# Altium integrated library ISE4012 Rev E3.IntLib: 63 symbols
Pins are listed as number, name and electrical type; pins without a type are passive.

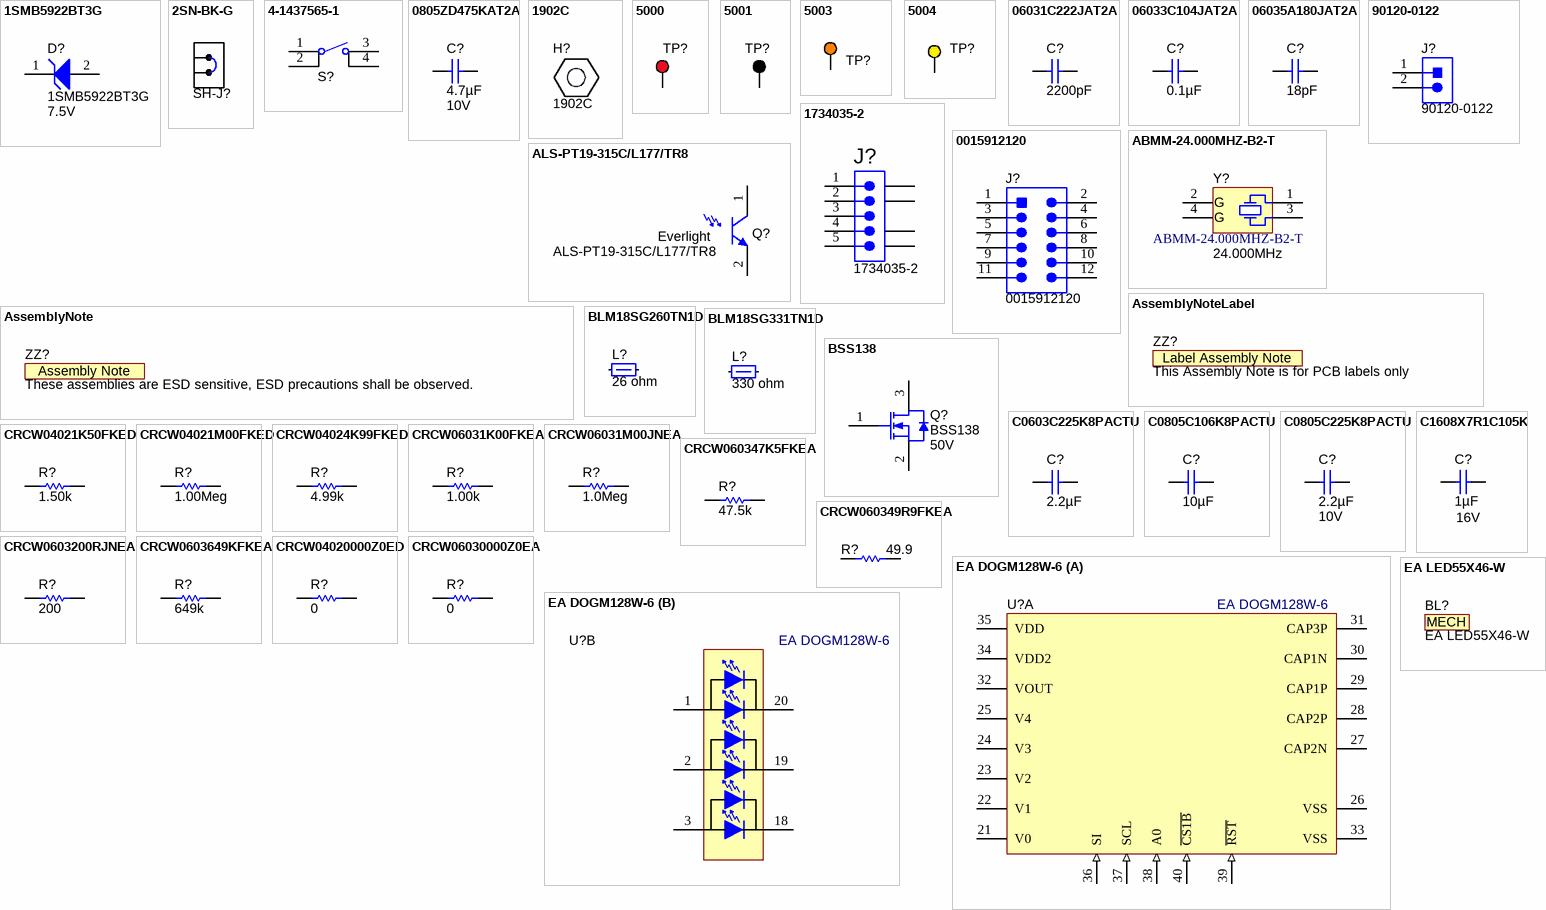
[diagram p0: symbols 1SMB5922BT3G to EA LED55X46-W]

## 1SMB5922BT3G
designator D?  value 7.5V
Diode, Zener, 7.5V, 550mW, SMB; Manufacturer: ON Semiconductor; U/M: EA; Power_W: 0.55; Vz_V: 7.5; Value1: 0.55W; RJA_CperW: 226
signal-integrity model Diode
simulation model 1smb5922bt3
footprint SMB
pins: 1 K, 2 A

## 2SN-BK-G
designator SH-J?  (value not drawn)
Shunt, 2mm, Gold plated, Black; Manufacturer: Samtec; Value: 1x2; Note: You can "mate" this to a header by matching the designator.  i.e. use SH-J3 for header J3
footprint 2SN-BK-G

## 4-1437565-1
designator S?  (value not drawn)
Switch, Tactile, SPST-NO, 0.05A, 12V, SMT; Manufacturer: TE Connectivity; SymbolCreator: a0412235; VDC_V: 12; SwitchFunction: Off-Mom; PositionCount: 1; CurrentRating_mA: 50
footprint SW_FSM4JSMA
pins: 1, 2, 3, 4

## 0805ZD475KAT2A
designator C?  ValueDisplayed: 4.7µF  Value2: 10V  (hidden comment: 0805ZD475KAT2A)
CAP, CERM, 4.7uF, 10V, +/-10%, X5R, 0805; Manufacturer: AVX; Polarized: N; CompType: Capacitor; U/M: EA; Cap_F: 0.0000047; Tolerance_%: 10; ESR_Ohm: 0.007; Value1: 0.007 ohm; TaMin_C: -55; TaMax_C: 85; Cap_Case: 0805
signal-integrity model Cap
simulation model Cap
footprint 0805_HV
footprint 0805
footprint 0805M
footprint 0805L
pins: 1, 2

## 1902C
designator H?
Standoff, Hex, 0.5"L #4-40 Nylon; Manufacturer: Keystone; CompType: Hardware
footprint Keystone_1902C

## 5000
designator TP?  (value not drawn)
Test Point, Miniature, Red, TH; Manufacturer: Keystone; CompType: Test Point Loop; U/M: EA
footprint Keystone5000
pins: 1

## 5001
designator TP?, comment 5000  (value not drawn)
Test Point, Miniature, Black, TH; PartNumber: 5001; Manufacturer: Keystone; CompType: Test Point Loop; U/M: EA
footprint Keystone5001
footprint Keystone5000
pins: 1

## 5003
designator TP?  (value not drawn)
Test Point, Miniature, Orange, TH; Manufacturer: Keystone; CompType: Test Point Loop; U/M: EA
footprint Keystone5003
pins: 1

## 5004
designator TP?  (value not drawn)
Test Point, Miniature, Yellow, TH; Manufacturer: Keystone; CompType: Test Point Loop; U/M: EA
footprint Keystone5004
pins: 1

## 06031C222JAT2A
designator C?  ValueDisplayed: 2200pF  (hidden comment: 06031C222JAT2A)
CAP, CERM, 2200pF, 100V, +/-5%, X7R, 0603; Manufacturer: AVX; Polarized: N; CompType: Capacitor; U/M: EA; Cap_F: 0.0000000022; Tolerance_%: 5; ESR_Ohm: 0.192; Value1: 0.192 ohm; VDC_V: 100; TaMin_C: -55; TaMax_C: 125; Cap_Case: 0603
signal-integrity model Cap
simulation model Cap
footprint 0603
footprint 0603M
footprint 0603L
footprint 0603_HV
pins: 1, 2

## 06033C104JAT2A
designator C?  ValueDisplayed: 0.1µF  (hidden comment: 06033C104JAT2A)
CAP, CERM, 0.1uF, 25V, +/-5%, X7R, 0603; Manufacturer: AVX; Polarized: N; CompType: Capacitor; U/M: EA; Cap_F: 0.0000001; Tolerance_%: 5; ESR_Ohm: 0.05; Value1: 0.05 ohm; VDC_V: 25; TaMin_C: -55; TaMax_C: 125; Cap_Case: 0603
signal-integrity model Cap
simulation model Cap
footprint 0603
footprint 0603M
footprint 0603L
footprint 0603_HV
pins: 1, 2

## 06035A180JAT2A
designator C?  ValueDisplayed: 18pF  (hidden comment: 06035A180JAT2A)
CAP, CERM, 18pF, 50V, +/-5%, C0G/NP0, 0603; Manufacturer: AVX; Polarized: N; CompType: Capacitor; U/M: EA; Cap_F: 0.000000000018; Tolerance_%: 5; ESR_Ohm: 0.289; Value1: 0.289 ohm; VDC_V: 50; TaMin_C: -55; TaMax_C: 125; Cap_Case: 0603
signal-integrity model Cap
simulation model Cap
footprint 0603
footprint 0603M
footprint 0603L
footprint 0603_HV
footprint 0603S
pins: 1, 2

## 90120-0122
designator J?
Header, 100mil, 2x1, Tin plated, TH; Manufacturer: Molex; SymbolCreator: a0412235; U/M: EA
footprint CONN_90120-0122
pins: 1, 2
1 alternate drawing of the same symbol

## 1734035-2
designator J?
Connector, Receptacle, Mini-USB Type B, R/A, Top Mount SMT; Manufacturer: TE Connectivity; SymbolCreator: A0412235; U/M: EA
footprint CONN_USB-Mini-B-1734035-2
pins: 1, 2, 3, 4, 5, 6 GND, 7 GND, 8 GND, 9 GND

## 0015912120
designator J?
Header, 6x2, 100mil, SMT; Manufacturer: Molex; SymbolCreator: a0412235; U/M: EA
footprint MOLEX_0015912120
pins: 1, 2, 3, 4, 5, 6, 7, 8, 9, 10, 11, 12
1 alternate drawing of the same symbol

## ABMM-24.000MHZ-B2-T
designator Y?  Frequency: 24.000MHz
Crystal, 24.000MHz, 18pF, SMD; Manufacturer: Abracon Corportation; SymbolCreator: a0412235; U/M: EA; TaMin_C: -20; TaMax_C: 70; Frequency Stability: ±50ppm
footprint Abracon_ABMM
pins: 1, 2 GND (power), 3, 4 GND (power)

## ALS-PT19-315C/L177/TR8
designator Q?  Manufacturer: Everlight  (hidden comment: ALS-PT19-315C/L177/TR8)
AMBIENT LIGHT SENSOR, SMD; Symbol Creator: a0411947
footprint ALS-PT19-315C-L177-TR8
pins: 1 C, 2 E

## AssemblyNote
designator ZZ?, comment These assemblies are ESD sensitive, ESD precautions shall be observed.  (no BOM)
SymbolCreator: codlsc; CompType: AssemblyNote
footprint AssemblyNote

## AssemblyNoteLabel
designator ZZ?, comment This Assembly Note is for PCB labels only  (no BOM)
SymbolCreator: a0412235
footprint AssemblyNoteLabel

## BLM18SG260TN1D
designator L?  value 26 ohm  (hidden comment: BLM18SG260TN1D)
6A Ferrite Bead, 26 ohm @ 100MHz, SMD; Manufacturer: MuRata; Imax_A: 6; DCR_ohm: 0.007; Value1: 0.007 ohm; ZTyp@100MHz_Ohm: 26; U/M: EA
footprint 0603 (0603 from SM-752 data)
footprint 0603M
footprint 0603L
footprint 0603_HV
footprint 0603S
pins: 1, 2

## BLM18SG331TN1D
designator L?  value 330 ohm  (hidden comment: BLM18SG331TN1D)
1.5A Ferrite Bead, 330 ohm @ 100MHz, SMD; Manufacturer: MuRata; Imax_A: 1.5; DCR_ohm: 0.07; Value1: 0.07 ohm; ZTyp@100MHz_Ohm: 330; U/M: EA
footprint 0603 (0603 from SM-752 data)
footprint 0603M
footprint 0603L
footprint 0603_HV
pins: 1, 2

## BSS138
designator Q?  value 50V
MOSFET, N-CH, 50V, 0.22A, SOT-23; Manufacturer: Fairchild Semiconductor; Alternate Manufacturer: None; U/M: EA; ChType: N; VdsMax_V: 50; Value1: 6 ohm; Rdson45_Ohm: 6; Value2: 1.7 nC; QgTyp_nC: 1.7; Vgs_V: 20; IdsMax_A: 0.22
footprint SOT-23
footprint SOT-23M
footprint SOT-23L
pins: 1 G, 2 S, 3 D

## C0603C225K8PACTU
designator C?  ValueDisplayed: 2.2µF  (hidden comment: C0603C225K8PACTU)
CAP, CERM, 2.2uF, 10V, +/-10%, X5R, 0603; Manufacturer: Kemet; Polarized: N; CompType: Capacitor; U/M: EA; Cap_F: 0.0000022; Tolerance_%: 10; Value1: Unknown; TaMin_C: -55; TaMax_C: 85; Cap_Case: 0603
signal-integrity model Cap
simulation model Cap
footprint 0603
footprint 0603M
footprint 0603L
footprint 0603_HV
footprint 0603S
pins: 1, 2

## C0805C106K8PACTU
designator C?  ValueDisplayed: 10µF  (hidden comment: C0805C106K8PACTU)
CAP, CERM, 10uF, 10V, +/-10%, X5R, 0805; Manufacturer: Kemet; Polarized: N; CompType: Capacitor; U/M: EA; Cap_F: 0.00001; Tolerance_%: 10; ESR_Ohm: 0.003; Value1: 0.003 ohm; IRMS_A: 11.43; TaMin_C: -55; TaMax_C: 85; Cap_Case: 0805
signal-integrity model Cap
simulation model Cap
footprint 0805_HV
footprint 0805
footprint 0805M
footprint 0805L
pins: 1, 2

## C0805C225K8PACTU
designator C?  ValueDisplayed: 2.2µF  Value2: 10V  (hidden comment: C0805C225K8PACTU)
CAP, CERM, 2.2uF, 10V, +/-10%, X5R, 0805; Manufacturer: Kemet; Polarized: N; CompType: Capacitor; U/M: EA; Cap_F: 0.0000022; Tolerance_%: 10; ESR_Ohm: 0.006; Value1: 0.006 ohm; IRMS_A: 7.32; TaMin_C: -55; TaMax_C: 85; Cap_Case: 0805
signal-integrity model Cap
simulation model Cap
footprint 0805_HV
footprint 0805
footprint 0805M
footprint 0805L
pins: 1, 2

## C1608X7R1C105K
designator C?  ValueDisplayed: 1µF  Value2: 16V  (hidden comment: C1608X7R1C105K)
CAP, CERM, 1uF, 16V, +/-10%, X7R, 0603; Manufacturer: TDK; Polarized: N; CompType: Capacitor; U/M: EA; Cap_F: 0.000001; Tolerance_%: 10; ESR_Ohm: 0.0057; Value1: 0.0057 ohm; VDC_V: 16; TaMin_C: -55; TaMax_C: 125; Cap_Case: 0603
signal-integrity model Cap
simulation model Cap
footprint 0603
footprint 0603M
footprint 0603L
footprint 0603_HV
footprint 0603S
pins: 1, 2

## CRCW04021K50FKED
designator R?  value 1.50k  (hidden comment: CRCW04021K50FKED)
RES, 1.50k ohm, 1%, 0.063W, 0402; Manufacturer: Vishay-Dale; CompType: Resistor; Res_ohm: 1500; Value_Code: 1k50; Tolerance_%: 1; Power_W: 0.063; VDC_V: 50; TempCo: 100 ppm/C; EIA_Code: E96; U/M: EA
signal-integrity model Resistor
simulation model Resistor
footprint 0402
footprint 0402M
footprint 0402L
pins: 1, 2

## CRCW04021M00FKED
designator R?  value 1.00Meg  (hidden comment: CRCW04021M00FKED)
RES, 1.00Meg ohm, 1%, 0.063W, 0402; Manufacturer: Vishay-Dale; CompType: Resistor; Res_ohm: 1000000; Value_Code: 1M00; Tolerance_%: 1; Power_W: 0.063; VDC_V: 50; TempCo: 100 ppm/C; EIA_Code: E96; U/M: EA
signal-integrity model Resistor
simulation model Resistor
footprint 0402
footprint 0402M
footprint 0402L
pins: 1, 2

## CRCW04024K99FKED
designator R?  value 4.99k  (hidden comment: CRCW04024K99FKED)
RES, 4.99k ohm, 1%, 0.063W, 0402; Manufacturer: Vishay-Dale; CompType: Resistor; Res_ohm: 4990; Value_Code: 4k99; Tolerance_%: 1; Power_W: 0.063; VDC_V: 50; TempCo: 100 ppm/C; EIA_Code: E96; U/M: EA
signal-integrity model Resistor
simulation model Resistor
footprint 0402
footprint 0402M
footprint 0402L
footprint 0402S
pins: 1, 2

## CRCW06031K00FKEA
designator R?  value 1.00k  (hidden comment: CRCW06031K00FKEA)
RES, 1.00k ohm, 1%, 0.1W, 0603; Manufacturer: Vishay-Dale; CompType: Resistor; Res_ohm: 1000; Value_Code: 1k00; Tolerance_%: 1; Power_W: 0.1; VDC_V: 75; TempCo: 100 ppm/C; EIA_Code: E96; U/M: EA
signal-integrity model Resistor
simulation model Resistor
footprint 0603
footprint 0603M
footprint 0603L
footprint 0603_HV
footprint 0603S
pins: 1, 2

## CRCW06031M00JNEA
designator R?  value 1.0Meg  (hidden comment: CRCW06031M00JNEA)
RES, 1.0Meg ohm, 5%, 0.1W, 0603; Manufacturer: Vishay-Dale; CompType: Resistor; Tolerance_%: 5; VDC_V: 75; Power_W: 0.1; Res_ohm: 1000000; Value_Code: 1M00; TempCo_ppm/C: 200; EIA_Code: E24; U/M: EA
signal-integrity model Resistor
simulation model Resistor
footprint 0603
footprint 0603M
footprint 0603L
footprint 0603_HV
pins: 1, 2

## CRCW060347K5FKEA
designator R?  value 47.5k  (hidden comment: CRCW060347K5FKEA)
RES, 47.5k ohm, 1%, 0.1W, 0603; Manufacturer: Vishay-Dale; CompType: Resistor; Res_ohm: 47500; Value_Code: 47k5; Tolerance_%: 1; Power_W: 0.1; VDC_V: 75; TempCo: 100 ppm/C; EIA_Code: E96; U/M: EA
signal-integrity model Resistor
simulation model Resistor
footprint 0603
footprint 0603M
footprint 0603L
footprint 0603_HV
pins: 1, 2

## CRCW060349R9FKEA
designator R?  value 49.9  (hidden comment: CRCW060349R9FKEA)
RES, 49.9 ohm, 1%, 0.1W, 0603; Manufacturer: Vishay-Dale; CompType: Resistor; Value_Code: 49R9; Tolerance_%: 1; Power_W: 0.1; VDC_V: 75; TempCo: 100 ppm/C; EIA_Code: E96; U/M: EA
signal-integrity model Resistor
simulation model Resistor
footprint 0603
footprint 0603M
footprint 0603L
footprint 0603_HV
pins: 1, 2

## CRCW0603200RJNEA
designator R?  value 200  (hidden comment: CRCW0603200RJNEA)
RES, 200 ohm, 5%, 0.1W, 0603; Manufacturer: Vishay-Dale; CompType: Resistor; Value_Code: 200R; Tolerance_%: 5; Power_W: 0.1; VDC_V: 75; TempCo: 200 ppm/C; EIA_Code: E24; U/M: EA
signal-integrity model Resistor
simulation model Resistor
footprint 0603
footprint 0603M
footprint 0603L
footprint 0603_HV
pins: 1, 2

## CRCW0603649KFKEA
designator R?  value 649k  (hidden comment: CRCW0603649KFKEA)
RES, 649k ohm, 1%, 0.1W, 0603; Manufacturer: Vishay-Dale; CompType: Resistor; Res_ohm: 649000; Tolerance_%: 1; Power_W: 0.1; VDC_V: 75; TempCo: 100 ppm/C; EIA_Code: E96; U/M: EA
signal-integrity model Resistor
simulation model Resistor
footprint 0603
footprint 0603M
footprint 0603L
footprint 0603_HV
footprint 0603S
pins: 1, 2

## CRCW04020000Z0ED
designator R?  value 0  (hidden comment: CRCW04020000Z0ED)
RES, 0 ohm, 5%, 0.063W, 0402; Manufacturer: Vishay-Dale; CompType: Resistor; Value_Code: 0000; Tolerance_%: 5; Power_W: 0.063; VDC_V: 50; TempCo: 200 ppm/C; EIA_Code: E24; U/M: EA
signal-integrity model Resistor
simulation model Resistor
footprint 0402
footprint 0402M
footprint 0402L
pins: 1, 2

## CRCW06030000Z0EA
designator R?  value 0  (hidden comment: CRCW06030000Z0EA)
RES, 0 ohm, 5%, 0.1W, 0603; Manufacturer: Vishay-Dale; CompType: Resistor; Value_Code: 0000; Tolerance_%: 5; Power_W: 0.1; VDC_V: 75; TempCo: 200 ppm/C; EIA_Code: E24; U/M: EA
signal-integrity model Resistor
simulation model Resistor
footprint 0603
footprint 0603M
footprint 0603L
footprint 0603_HV
pins: 1, 2

## EA DOGM128W-6
designator U?
Module, 128x64-pixel graphics display; Manufacturer: Electronic Assembly; SymbolCreator: a0799628
footprint LCD-MODULE_EA DOGM128W-6
part A pins: 21 V0 (power), 22 V1 (power), 23 V2 (power), 24 V3 (power), 25 V4 (power), 26 VSS (power), 27 CAP2N, 28 CAP2P, 29 CAP1P, 30 CAP1N, 31 CAP3P, 32 VOUT (power), 33 VSS (power), 34 VDD2 (power), 35 VDD (power), 36 SI (in), 37 SCL (in), 38 A0 (in), 39 ~{RST} (in), 40 ~{CS1B} (in)
part B pins: 1 A, 2 A, 3 A, 18 K, 19 K, 20 K

## EA LED55X46-W
designator BL?  (mechanical)
LED Backlight, White; Manufacturer: Electronic Assembly; SymbolCreator: codlsc

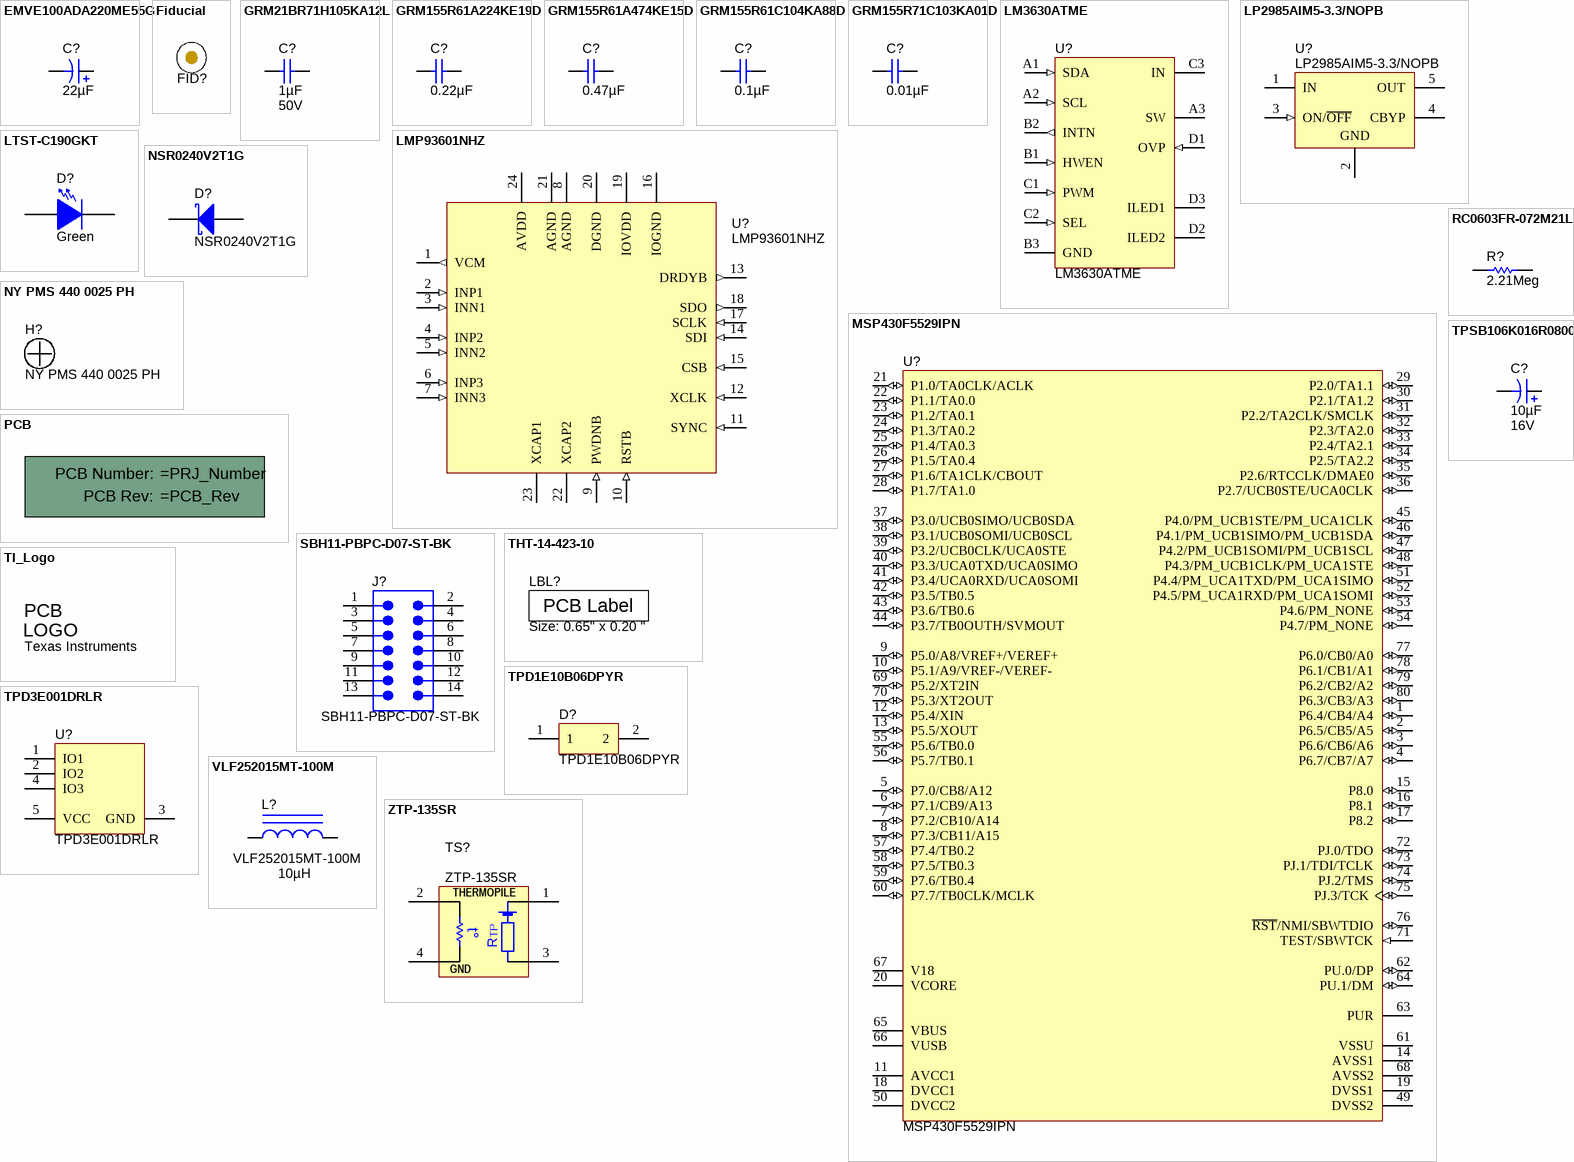
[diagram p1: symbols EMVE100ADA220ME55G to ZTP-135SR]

## EMVE100ADA220ME55G
designator C?, comment ValueDisplayed: 22µF  (hidden comment: EEE-1AA220WR)
CAP ALUM 22UF 10V 20% SMD; Manufacturer: Panasonic - ECG; Polarized: Y; CompType: Capacitor; U/M: EA; Cap_F: 0.000022; Tolerance_%: 20; VDC_V: 10; IRMS_A: 0.03; TaMin_C: -40; TaMax_C: 105; Cap_Case: E55
signal-integrity model Cap
simulation model Cap
footprint CAPSMT_62_E55 (5 x 5.2mm:  Chemi-Con E55)
pins: 1 +, 2 -

## Fiducial
designator FID?  (value not drawn)
Fiducial mark.  There is nothing to buy or mount.; SymbolCreator: codlsc
footprint Fiducial10-30
footprint Fiducial10-20
footprint Fiducial15-30
footprint Fiducial20-40
footprint Fiducial6.4-20
footprint Fiducial10-30_TopLayerKeepOutOnly
footprint Fiducial6.4-20_TopLayerKeepOutOnly
footprint Fiducial10-20_TopLayerKeepOutOnly
footprint Fiducial15-30_TopLayerKeepOutOnly
footprint Fiducial20-40_TopLayerKeepOutOnly

## GRM21BR71H105KA12L
designator C?  ValueDisplayed: 1µF  Value2: 50V  (hidden comment: GRM21BR71H105KA12L)
CAP, CERM, 1uF, 50V, +/-10%, X7R, 0805; Manufacturer: MuRata; Polarized: N; CompType: Capacitor; U/M: EA; Cap_F: 0.000001; Tolerance_%: 10; Value1: Unknown; VDC_V: 50; TaMin_C: -55; TaMax_C: 125; Cap_Case: 0805
signal-integrity model Cap
simulation model Cap
footprint 0805_HV
footprint 0805
footprint 0805M
footprint 0805L
pins: 1, 2

## GRM155R61A224KE19D
designator C?  ValueDisplayed: 0.22µF  (hidden comment: GRM155R61A224KE19D)
CAP, CERM, 0.22uF, 10V, +/-10%, X5R, 0402; Manufacturer: MuRata; Polarized: N; CompType: Capacitor; U/M: EA; Cap_F: 0.00000022; Tolerance_%: 10; Value1: Unknown; TaMin_C: -55; TaMax_C: 85; Cap_Case: 0402
signal-integrity model Cap
simulation model Cap
footprint 0402
footprint 0402M
footprint 0402L
pins: 1, 2

## GRM155R61A474KE15D
designator C?  ValueDisplayed: 0.47µF  (hidden comment: GRM155R61A474KE15D)
CAP, CERM, 0.47uF, 10V, +/-10%, X5R, 0402; Manufacturer: MuRata; Polarized: N; CompType: Capacitor; U/M: EA; Cap_F: 0.00000047; Tolerance_%: 10; Value1: Unknown; TaMin_C: -55; TaMax_C: 85; Cap_Case: 0402
signal-integrity model Cap
simulation model Cap
footprint 0402
footprint 0402M
footprint 0402L
pins: 1, 2

## GRM155R61C104KA88D
designator C?  ValueDisplayed: 0.1µF  (hidden comment: GRM155R61C104KA88D)
CAP, CERM, 0.1uF, 16V, +/-10%, X5R, 0402; Manufacturer: MuRata; Polarized: N; CompType: Capacitor; U/M: EA; Cap_F: 0.0000001; Tolerance_%: 10; Value1: Unknown; VDC_V: 16; TaMin_C: -55; TaMax_C: 85; Cap_Case: 0402
signal-integrity model Cap
simulation model Cap
footprint 0402
footprint 0402M
footprint 0402L
pins: 1, 2

## GRM155R71C103KA01D
designator C?  ValueDisplayed: 0.01µF  (hidden comment: GRM155R71C103KA01D)
CAP, CERM, 0.01uF, 16V, +/-10%, X7R, 0402; Manufacturer: MuRata; Polarized: N; CompType: Capacitor; U/M: EA; Cap_F: 0.00000001; Tolerance_%: 10; Value1: Unknown; VDC_V: 16; TaMin_C: -55; TaMax_C: 125; Cap_Case: 0402
signal-integrity model Cap
simulation model Cap
footprint 0402
footprint 0402M
footprint 0402L
footprint 0402S
pins: 1, 2

## LM3630ATME
designator U?
LM3630A High-Efficiency Dual-String White LED Driver, YFQ0012AKAR; Alternate Manufacturer: None; Manufacturer: Texas Instruments; SymbolCreator: a0411947; CompType: IC; U/M: EA
footprint YFQ0012AKAR
pins: A1 SDA (in), A2 SCL (in), A3 SW (power), B1 HWEN (in), B2 INTN (out), B3 GND (power), C1 PWM (in), C2 SEL (in), C3 IN (power), D1 OVP (in), D2 ILED2 (power), D3 ILED1 (power)

## LMP93601NHZ
designator U?
16-bit analog-front-end for thermopile occupancy detector arrays, NHZ0024B; Alternate Manufacturer: None; Manufacturer: Texas Instruments; SymbolCreator: a0412235; CompType: IC; U/M: EA
footprint NHZ0024B
pins: 1 VCM (out), 2 INP1 (in), 3 INN1 (in), 4 INP2 (in), 5 INN2 (in), 6 INP3 (in), 7 INN3 (in), 8 AGND (power), 9 PWDNB (in), 10 RSTB (in), 11 SYNC (in), 12 XCLK (in), 13 DRDYB (out), 14 SDI (in), 15 CSB (in), 16 IOGND (power), 17 SCLK (in), 18 SDO (out), 19 IOVDD (power), 20 DGND (power), 21 AGND (power), 22 XCAP2, 23 XCAP1, 24 AVDD (power)

## LP2985AIM5-3.3/NOPB
designator U?
Micropower 150 mA Low-Noise Ultra Low-Dropout Regulator, 5-pin SOT-23, Pb-Free; Manufacturer: National Semiconductor; PackageTopMarking: L0RA*XTT; PowerWise: N; CompType: LDO IC
footprint MF05A_N (SOT23, 5-Leads, Body 2.9x1.6mm, Pitch 0.95mm, Lead Span 2.8mm, IPC Medium Density)
footprint MF05A_L (SOT23, 5-Leads, Body 2.9x1.6mm, Pitch 0.95mm, Lead Span 2.8mm, IPC High Density)
footprint MF05A_M (SOT23, 5-Leads, Body 2.9x1.6mm, Pitch 0.95mm, Lead Span 2.8mm, IPC Low Density)
pins: 1 IN (power), 2 GND (power), 3 ON/~{OFF} (in), 4 CBYP, 5 OUT (power)

## LTST-C190GKT
designator D?  value Green  (hidden comment: LTST-C190GKT)
LED, Green, SMD; Manufacturer: Lite-On; Vf_V: 2.1; Value2: 2.1V; Io_A: 0.02; Power_TotalModule: 0.1; Value1: 0.1W; U/M: EA
footprint LED_LTST-C171 (LITE-ON)
pins: 1 A, 2 K

## MSP430F5529IPN
designator U?
Mixed Signal MicroController, PN0080A; Alternate Manufacturer: None; Manufacturer: Texas Instruments; ADC: 12-bit SAR; ADC Channels: 16; Brown Out Reset: Yes; DMA: 3; Eco-Plan: Green (RoHS & no Sb/Br); Flash(KB): 128; Frequency(MHz): 25; GPIO: 63; Multiplier: 32x32; SRAM(B): 8192; SubFamily: 5 Series; Timers - 16-bit: 4; USB: 1; USCI_A (UART/LIN/IrDA/SPI): 2; SymbolCreator: Altium/a0412235; CompType: IC; U/M: EA
footprint PN0080A_N
footprint PN0080A_M
footprint PN0080A_L
pins: 1 P6.4/CB4/A4 (io), 2 P6.5/CB5/A5 (io), 3 P6.6/CB6/A6 (io), 4 P6.7/CB7/A7 (io), 5 P7.0/CB8/A12 (io), 6 P7.1/CB9/A13 (io), 7 P7.2/CB10/A14 (io), 8 P7.3/CB11/A15 (io), 9 P5.0/A8/VREF+/VEREF+ (io), 10 P5.1/A9/VREF-/VEREF- (io), 11 AVCC1 (power) "Analog power supply", 12 P5.4/XIN (io), 13 P5.5/XOUT (io), 14 AVSS1 (power) "Analog ground supply", 15 P8.0 (io) "General-purpose digital I/O", 16 P8.1 (io) "General-purpose digital I/O", 17 P8.2 (io) "General-purpose digital I/O", 18 DVCC1 (power) "Digital power supply", 19 DVSS1 (power) "Digital ground supply", 20 VCORE "Regulated core power supply output (internal use only, no external current loading)", 21 P1.0/TA0CLK/ACLK (io), 22 P1.1/TA0.0 (io), 23 P1.2/TA0.1 (io), 24 P1.3/TA0.2 (io), 25 P1.4/TA0.3 (io), 26 P1.5/TA0.4 (io), 27 P1.6/TA1CLK/CBOUT (io), 28 P1.7/TA1.0 (io), 29 P2.0/TA1.1 (io), 30 P2.1/TA1.2 (io), 31 P2.2/TA2CLK/SMCLK (io), 32 P2.3/TA2.0 (io), 33 P2.4/TA2.1 (io), 34 P2.5/TA2.2 (io), 35 P2.6/RTCCLK/DMAE0 (io), 36 P2.7/UCB0STE/UCA0CLK (io), 37 P3.0/UCB0SIMO/UCB0SDA (io), 38 P3.1/UCB0SOMI/UCB0SCL (io), 39 P3.2/UCB0CLK/UCA0STE (io), 40 P3.3/UCA0TXD/UCA0SIMO (io), 41 P3.4/UCA0RXD/UCA0SOMI (io), 42 P3.5/TB0.5 (io), 43 P3.6/TB0.6 (io), 44 P3.7/TB0OUTH/SVMOUT (io), 45 P4.0/PM_UCB1STE/PM_UCA1CLK (io), 46 P4.1/PM_UCB1SIMO/PM_UCB1SDA (io), 47 P4.2/PM_UCB1SOMI/PM_UCB1SCL (io), 48 P4.3/PM_UCB1CLK/PM_UCA1STE (io), 49 DVSS2 (power) "Digital ground supply", 50 DVCC2 (power) "Digital power supply", 51 P4.4/PM_UCA1TXD/PM_UCA1SIMO (io), 52 P4.5/PM_UCA1RXD/PM_UCA1SOMI (io), 53 P4.6/PM_NONE (io), 54 P4.7/PM_NONE (io), 55 P5.6/TB0.0 (io), 56 P5.7/TB0.1 (io), 57 P7.4/TB0.2 (io), 58 P7.5/TB0.3 (io), 59 P7.6/TB0.4 (io), 60 P7.7/TB0CLK/MCLK (io), 61 VSSU (power) "USB PHY ground supply", 62 PU.0/DP (io), 63 PUR "USB pullup resistor pin (open drain). The voltage level at the PUR pin is used to invoke the default USB BSL. Recommended 1-Mohm resistor to ground.", 64 PU.1/DM (io), 65 VBUS (power) "USB LDO input (connect to USB power source)", 66 VUSB (power) "USB LDO output", 67 V18 "USB regulated power (internal use only, no external current loading)", 68 AVSS2 (power) "Analog ground supply", 69 P5.2/XT2IN (io), 70 P5.3/XT2OUT (io), 71 TEST/SBWTCK (in), 72 PJ.0/TDO (io), 73 PJ.1/TDI/TCLK (io), 74 PJ.2/TMS (io), 75 PJ.3/TCK (io), 76 ~{RST}/NMI/SBWTDIO (io), 77 P6.0/CB0/A0 (io), 78 P6.1/CB1/A1 (io), 79 P6.2/CB2/A2 (io), 80 P6.3/CB3/A3 (io)
1 alternate drawing of the same symbol

## NSR0240V2T1G
designator D?
Diode, Schottky, 40V, 0.25A, SOD-523; Manufacturer: ON Semiconductor; U/M: EA; Vf_V: 0.7; Value2: 0.7V; Io_A: 0.25; Vr_V: 40; TJmax_C: 150; RJC_CperW: 600
signal-integrity model Diode
footprint SOD-523
pins: 1 K, 2 A

## NY PMS 440 0025 PH
designator H?
Machine Screw, Round, #4-40 x 1/4, Nylon, Philips panhead; Manufacturer: B&F Fastener Supply; CompType: Hardware; SymbolCreator: codlsc; U/M: EA
footprint NY PMS 440 0025 PH

## PCB
designator !PCB?, comment Printed Circuit Board  (value not drawn)  (mechanical)
Manufacturer: Any; SymbolCreator: a0412235; CompType: PCB
1 alternate drawing of the same symbol

## RC0603FR-072M21L
designator R?  value 2.21Meg  (hidden comment: RC0603FR-072M21L)
RES, 2.21Meg ohm, 1%, 0.1W, 0603; Manufacturer: Yageo America; CompType: Resistor; Res_ohm: 2210000; Value_Code: 2M21; Tolerance_%: 1; Power_W: 0.1; VDC_V: 150; TempCo: 200 ppm/C; EIA_Code: E96; U/M: EA
signal-integrity model Resistor
simulation model Resistor
footprint 0603
footprint 0603M
footprint 0603L
footprint 0603_HV
pins: 1, 2

## SBH11-PBPC-D07-ST-BK
designator J?
Header (shrouded), 100 mil, 7x2, Gold plated, TH; Manufacturer: Sullins Connector Solutions; SymbolCreator: a0412235; CompType: Connector; U/M: EA
footprint CONN_SBH11-PBPC-D07-ST-BK
pins: 1, 2, 3, 4, 5, 6, 7, 8, 9, 10, 11, 12, 13, 14

## THT-14-423-10
designator LBL?, comment Size: 0.65" x 0.20 "
Thermal Transfer Printable Labels, 0.650" W x 0.200" H - 10,000 per roll; Manufacturer: Brady; PartNumber: THT-14-423-10; SymbolCreator: a0412235; CompType: Label
footprint Label_650x200

## TI_Logo
designator Logo?, comment Texas Instruments  (no BOM)
Texas Instrument Corporate Signature; SymbolCreator: a0412235
footprint TI_Stacked_SolderMask_Medium
footprint TI_Stacked_SolderMask_Medium_Vertical
footprint TI_Stacked_SolderMask_Small
footprint TI_Stacked_SolderMask_Small_Vertical
footprint TI_Stacked_Overlay_Medium
footprint TI_Stacked_Overlay_Medium_Vertical
footprint TI_Stacked_Overlay_Small
footprint TI_Stacked_Overlay_Small_Vertical
footprint TI_Horizontal_SolderMask_Small
footprint TI_Horizontal_Overlay_Medium
footprint TI_Horizontal_Overlay_Small
footprint TI_Symbol_SolderMask_Medium
footprint TI_Symbol_SolderMask_Small
footprint TI_Symbol_Overlay_Medium
footprint TI_Symbol_Overlay_Small
footprint TI_Horizontal_SolderMask_Medium

## TPD1E10B06DPYR
designator D?
ESD in 0402 Package with 10 pF Capacitance and 6 V Breakdown, 1 Channel, -40 to +125 degC, 2-pin X2SON (DPY), Green (RoHS & no Sb/Br); Manufacturer: Texas Instruments; Alternate Manufacturer: None; Alternate PartNumber: Equivalent; Breakdown Voltage(Min)(V): 6; Eco-Plan: TBD; IEC 61000-4-2 Air-Gap(+/- kV): 30; IO Capacitance(Typ)(pF): 10; SubFamily: ESD Solution
footprint DPY0002A_N (DFN, 2-Leads, Body 1.0x0.6x0.4mm, IPC Medium Density)
footprint DPY0002A_L (DFN, 2-Leads, Body 1.0x0.6x0.4mm, IPC High Density)
footprint DPY0002A_M (DFN, 2-Leads, Body 1.0x0.6x0.4mm, IPC Low Density)
pins: 1, 2

## TPD3E001DRLR
designator U?
Low-Capacitance + / - 15 kV ESD-Protection Array for High-Speed Data Interfaces, 3 Channels, -40 to +85 degC, 5-pin SOT (DRL), Green (RoHS & no Sb/Br); Manufacturer: Texas Instruments; Alternate Manufacturer: None; Alternate PartNumber: Equivalent; Breakdown Voltage(Min)(V): 11; IEC 61000-4-2 Air-Gap(+/- kV): 15; IEC 61000-4-2 Contact(+/- kV): 8; IO Capacitance(Typ)(pF): 1.5; IO Leakage Current(nA): 1; SubFamily: ESD Solution; USB High Speed: TRUE
footprint DRL0005A (SOTFL, 5-Flat Leads, Body 1.2x1.6x0.6mm, Pitch 0.5mm, TI Recommended)
footprint DRL0005A_N (SOTFL, 5-Flat Leads, Body 1.2x1.6x0.6mm, Pitch 0.5mm, IPC Medium Density)
footprint DRL0005A_L (SOTFL, 5-Flat Leads, Body 1.2x1.6x0.6mm, Pitch 0.5mm, IPC High Density)
footprint DRL0005A_M (SOTFL, 5-Flat Leads, Body 1.2x1.6x0.6mm, Pitch 0.5mm, IPC Low Density)
pins: 1 IO1 "ESD-protected channel", 2 IO2 "ESD-protected channel", 3 GND (power) "Ground", 4 IO3 "ESD-protected channel", 5 VCC (power) "Power-supply input. Bypass VCC to GND with a 0.1-uF ceramic Capacitor."

## TPSB106K016R0800
designator C?  ValueDisplayed: 10µF  Value2: 16V  (hidden comment: TPSB106K016R0800)
CAP, TANT, 10uF, 16V, +/-10%, 0.8 ohm, 3528-21 SMD; Manufacturer: AVX; Polarized: Y; CompType: Capacitor; U/M: EA; Cap_F: 0.00001; Tolerance_%: 10; Value1: 0.8 ohm; VDC_V: 16; ESR_Ohm: 0.8; IRMS_A: 0.293; TaMin_C: -55; TaMax_C: 125; Cap_Case: B
signal-integrity model Cap
simulation model Cap
footprint 3528-21
pins: 1 +, 2 -

## VLF252015MT-100M
designator L?  ValueDisplayed: 10µH
Inductor, Shielded, Ferrite, 10uH, 0.47A, 0.24 ohm, SMD; Manufacturer: TDK; Ind_H: 10.0E-6; Imax_A: 0.47; Irms: 0.94A @ 40C rise; Isat: 0.47A @ 30% inductance drop; DCR_ohm: 0.24
signal-integrity model Inductor
simulation model Inductor
footprint IND_VLF252015
pins: 1, 2

## ZTP-135SR
designator TS?
Thermopile IR Sensor, TO-46; Manufacturer: Amphenol RF; SymbolCreator: a0799628
footprint TO-46
pins: 1 OUT, 1, 2 IN, 2, 3 OUT, 4 IN (power)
